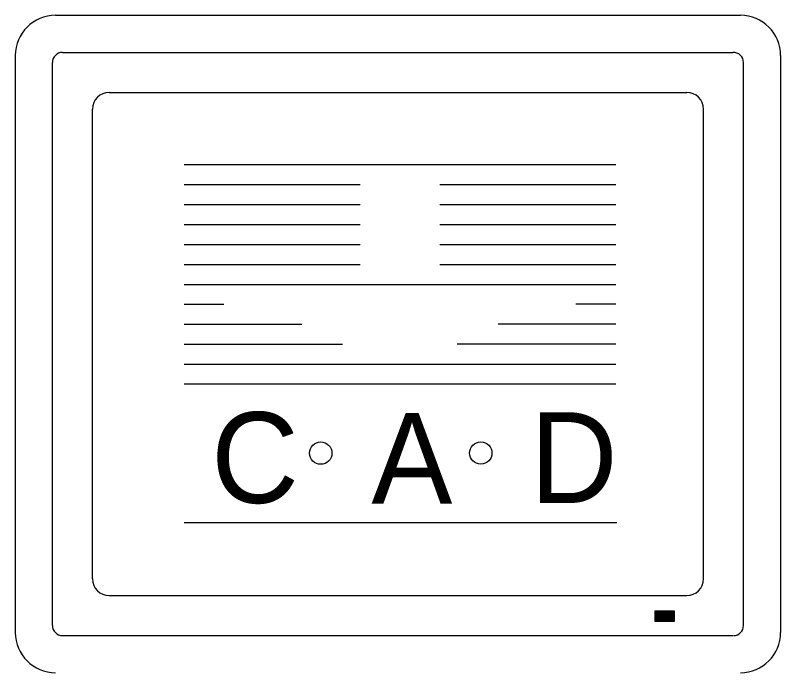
# Model space of a CAD drawing. Extents: x 22369.6 to 22428.3, y 22369.6 to 22415.
# Drawn here: x 22420.936 to 22422.608, y 22372.105 to 22373.542 of the extents above; entities that cross this region are included whole.
import ezdxf

# ---------------------------------------------------------------- set-up
doc = ezdxf.new("R2010")
doc.units = 0
for name, color, linetype in [('Level 2', 7, 'Continuous'), ('Level 3', 7, 'Continuous'), ('Level 5', 7, 'Continuous')]:
    doc.layers.add(name, color=color, linetype=linetype)

msp = doc.modelspace()

# ---------------------------------------------------------------- linework, layer by layer
at = {"layer": 'Level 2'}
for p, q in [((22421.1413, 22373.3733), (22422.4029, 22373.3733)), ((22421.1046, 22372.3101), (22421.1046, 22373.3366)), ((22422.4396, 22372.3101), (22422.4396, 22373.3366)), ((22421.1413, 22372.2735), (22422.4029, 22372.2735)), ((22422.3338, 22372.239), (22422.3756, 22372.239)), ((22422.3338, 22372.2378), (22422.3756, 22372.2378)), ((22422.3338, 22372.2365), (22422.3756, 22372.2365)), ((22422.3338, 22372.235), (22422.3756, 22372.235)), ((22422.3338, 22372.2336), (22422.3756, 22372.2336)), ((22422.3338, 22372.2325), (22422.3756, 22372.2325)), ((22422.3338, 22372.2311), (22422.3756, 22372.2311)), ((22422.3338, 22372.2298), (22422.3756, 22372.2298)), ((22422.3338, 22372.2285), (22422.3756, 22372.2285)), ((22422.3338, 22372.2271), (22422.3756, 22372.2271)), ((22422.3338, 22372.2258), (22422.3756, 22372.2258)), ((22422.3338, 22372.2245), (22422.3756, 22372.2245)), ((22422.3338, 22372.2233), (22422.3756, 22372.2233)), ((22422.3338, 22372.2218), (22422.3756, 22372.2218)), ((22422.3338, 22372.2205), (22422.3756, 22372.2205)), ((22422.3338, 22372.2193), (22422.3756, 22372.2193)), ((22422.3338, 22372.218), (22422.3756, 22372.218))]:
    msp.add_line(p, q, dxfattribs=at)
msp.add_lwpolyline([(22422.3338, 22372.24), (22422.3756, 22372.24), (22422.3756, 22372.2168), (22422.3338, 22372.2168)], close=True, dxfattribs=at)
for centre in [(22421.6033, 22372.5849), (22421.9529, 22372.5851)]:
    msp.add_circle(centre, 0.0244, dxfattribs=at)
for centre, start, end in [((22421.1412, 22373.3366), 90, 180), ((22422.4029, 22373.3366), 0, 90), ((22421.1412, 22372.3102), 180, 270), ((22422.4029, 22372.3102), 270, 0)]:
    msp.add_arc(centre, 0.0367, start, end, dxfattribs=at)
at = {"layer": 'Level 3'}
for p, q in [((22421.0241, 22373.5418), (22422.5201, 22373.5418)), ((22421.0393, 22373.4606), (22422.5034, 22373.4606)), ((22420.9361, 22372.193), (22420.9361, 22373.4538)), ((22421.0173, 22372.2083), (22421.0173, 22373.4386)), ((22422.5269, 22372.2083), (22422.5269, 22373.4386)), ((22422.6081, 22372.193), (22422.6081, 22373.4538)), ((22421.0393, 22372.1863), (22422.5034, 22372.1863))]:
    msp.add_line(p, q, dxfattribs=at)
for centre, radius, start, end in [((22421.024, 22373.4538), 0.088, 90, 180), ((22422.52, 22373.4538), 0.088, 0, 90), ((22421.0392, 22373.4386), 0.022, 90, 180), ((22422.5049, 22373.4386), 0.022, 0, 93.8704), ((22421.0392, 22372.2082), 0.022, 180, 270), ((22422.5049, 22372.2082), 0.022, 270, 0), ((22421.024, 22372.193), 0.088, 180, 270), ((22422.52, 22372.193), 0.088, 270, 0)]:
    msp.add_arc(centre, radius, start, end, dxfattribs=at)
at = {"layer": 'Level 5'}
for p, q in [((22421.3048, 22373.2155), (22422.2481, 22373.2155)), ((22421.3048, 22373.1718), (22421.6893, 22373.1718)), ((22421.8634, 22373.1718), (22422.2481, 22373.1718)), ((22421.3048, 22373.1283), (22421.6893, 22373.1283)), ((22421.8634, 22373.1283), (22422.2481, 22373.1283)), ((22421.3048, 22373.0848), (22421.6893, 22373.0848)), ((22421.8634, 22373.0848), (22422.2481, 22373.0848)), ((22421.3048, 22373.0411), (22421.6893, 22373.0411)), ((22421.8634, 22373.0411), (22422.2481, 22373.0411)), ((22421.3048, 22372.9975), (22421.6893, 22372.9975)), ((22421.8634, 22372.9975), (22422.2481, 22372.9975)), ((22421.3048, 22372.9538), (22422.2481, 22372.9538)), ((22421.3048, 22372.9105), (22421.3919, 22372.9105)), ((22422.2479, 22372.9105), (22422.1608, 22372.9105)), ((22421.3048, 22372.8668), (22421.5618, 22372.8668)), ((22422.2479, 22372.8668), (22421.9909, 22372.8668)), ((22421.3048, 22372.8233), (22421.6511, 22372.8233)), ((22422.2479, 22372.8233), (22421.9016, 22372.8233)), ((22421.3048, 22372.7796), (22422.2481, 22372.7796)), ((22421.3048, 22372.736), (22422.2481, 22372.736)), ((22421.3048, 22372.4335), (22422.2498, 22372.4335))]:
    msp.add_line(p, q, dxfattribs=at)

# ---------------------------------------------------------------- texts
for s, p in [('C', (22421.3639, 22372.476)), ('A', (22421.7139, 22372.4743)), ('D', (22422.0603, 22372.476))]:
    msp.add_text(s, height=0.1984, dxfattribs=at).set_placement(p)

doc.saveas('drawing.dxf')
